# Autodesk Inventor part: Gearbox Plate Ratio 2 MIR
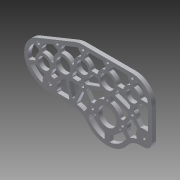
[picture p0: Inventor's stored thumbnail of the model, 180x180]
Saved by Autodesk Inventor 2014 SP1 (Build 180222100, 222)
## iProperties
Created: 2014-11
Part Number: Gearbox Plate Ratio 2 MIR
Material: Generic
Document SubType Name: Modeling
Designer: Michael
Density: 1 g/cm^3
Appearance: Default
Author: Michael
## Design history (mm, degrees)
derived "Gearbox Plate Ratio 2.ipt"
feature "Solid1::Gearbox Plate Ratio 2.ipt" dims "d0" = 10
tag "TaggingFeature1"
body "Solid1"
